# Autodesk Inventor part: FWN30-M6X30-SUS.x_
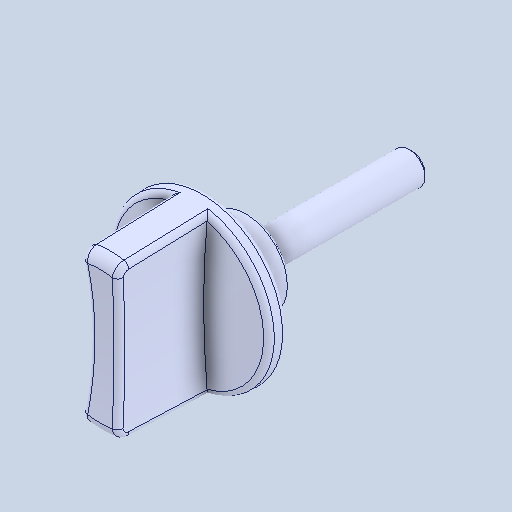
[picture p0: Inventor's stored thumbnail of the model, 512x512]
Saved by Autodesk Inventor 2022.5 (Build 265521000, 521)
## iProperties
Created: 2024-05
Part Number: FWN30-M6X30-SUS.x_
Material: 一般
Document SubType Name: Modeling
Designer: ImaoCorp
Density: 1 g/cm^3
Appearance: 既定
Author: ImaoCorp
Sending System: SOLIDWORKS 2022-2022290
MC: AMD64
MC_MODEL: Intel64 Family 6 Model 60 Stepping 3, GenuineIntel
OS: Windows_NT
FRU: Parasolid Version 33.1, build 260,  4-25-2022
FORMAT: text
GUISE: transmit
KEY: FILEFWN30-M6X30-SUS.x_t
DATE: Mon May 20 16:40:33 2024
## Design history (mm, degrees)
feature "Base1"
node "ソリッド1"
